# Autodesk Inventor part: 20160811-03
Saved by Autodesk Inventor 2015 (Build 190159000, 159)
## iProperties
Created: 2016-08
Part Number: 20160811-03
Material: Mosaz, měkká žlutá
Document SubType Name: Modeling
Designer: navara
Density: 8.47 g/cm^3
Appearance: Mosaz – satén
Author: navara
Beppe: 20160811-03.ipt
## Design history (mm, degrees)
feature "Base1"
node "Těleso1"
